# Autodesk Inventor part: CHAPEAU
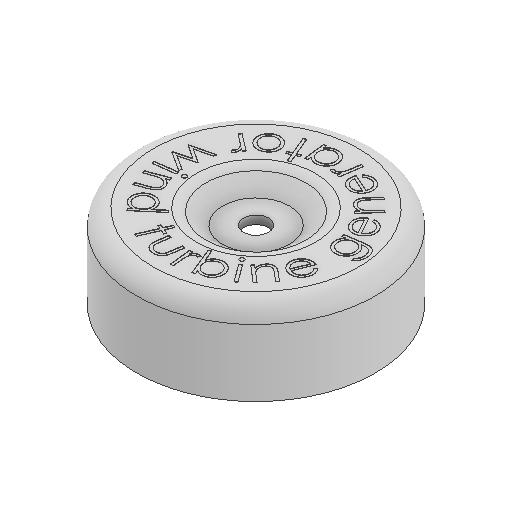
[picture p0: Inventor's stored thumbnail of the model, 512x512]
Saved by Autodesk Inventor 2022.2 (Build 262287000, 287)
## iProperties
Created: 2025-01
Part Number: CHAPEAU
Material: Generico
Document SubType Name: Modeling
Designer: 18907419
Density: 1 g/cm^3
Appearance: Default
Author: 18907419
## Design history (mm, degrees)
feature "CHAPEAU"
node "Solido1"
